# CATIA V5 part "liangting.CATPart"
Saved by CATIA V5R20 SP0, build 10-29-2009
Part number: liangting
Bounding box of the stored display mesh (mm): x -264.541 to 80, y -195 to 195, z -25 to 287.893
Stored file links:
  C:\Users\此生不败\Desktop\180211216李云飞\liangting.CATPart
  C:\Program Files\Dassault Systemes\B20\win_b64\startup\materials\Catalog.CATMaterial
  C:\Program Files\Dassault Systemes\B20\win_b64\startup\materials\bright_oak.jpg
  C:\Program Files\Dassault Systemes\B20\win_b64\startup\materials\alabaster.jpg
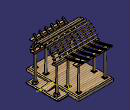
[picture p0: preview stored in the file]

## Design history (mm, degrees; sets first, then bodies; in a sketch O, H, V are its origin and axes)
Body1 (main body), material "Fence 3"
  Sketch1 on yz-plane, origin (0, 0, 0), H (0, 1, 0), V (0, 0, 1)
    line L1 (-120, -15) -> (120, -15)
    line L2 (120, -15) -> (120, -25)
    line L3 (120, -25) -> (-120, -25)
    line L4 (-120, -25) -> (-120, -15)
    distance O L1 = 15
    distance O L2 = 120
    distance O L4 = 120
    horizontal: L1 H, L3 H
    vertical: L2 V, L4 V
  Pad1: profile Sketch1, direction (1, 0, 0), length 80
  Sketch2 on xy-plane, origin (0, 0, 0), H (1, 0, 0), V (0, 1, 0)
    line L1 (-260, 195) -> (0, 195)
    line L2 (0, 195) -> (0, -195)
    line L3 (0, -195) -> (-260, -195)
    line L4 (-260, -195) -> (-260, 195)
    point P3 (0, -195)
    length L1 = 260
    distance O L1 = 195
    distance O L3 = 195
    horizontal: L1 H, L3 H
    vertical: L2 V, L4 V
    coincidence: P3 V
  Pad2: profile Sketch2, direction (0, 0, -1), length 25
  Chamfer1: length 6, angle 45, on edge [face of Pad2 from Sketch2.L1 | start face of Pad2]; edge [face of Pad2 from Sketch2.L4 | start face of Pad2]; edge [face of Pad2 from Sketch2.L3 | start face of Pad2]; edge [face of Pad2 from Sketch2.L2 | start face of Pad2]; edge [face of Pad1 from Sketch1.L1 | face of Pad1 from Sketch1.L2]; edge [face of Pad1 from Sketch1.L1 | end face of Pad1]; edge [face of Pad1 from Sketch1.L4 | face of Pad1 from Sketch1.L1]
  Sketch3 on xy-plane, origin (0, 0, 0), H (1, 0, 0), V (0, 1, 0)
    line L1 (-240, 175) -> (-215, 175)
    line L2 (-215, 175) -> (-215, 150)
    line L3 (-215, 150) -> (-240, 150)
    line L4 (-240, 150) -> (-240, 175)
    point P5 (-240, 95)
    line L5 (-240, 95) -> (-215, 95)
    line L6 (-215, 95) -> (-215, 70)
    line L7 (-215, 70) -> (-240, 70)
    line L8 (-240, 70) -> (-240, 95)
    point P7 (-215, 70)
    point P9 (-45, 175)
    line L9 (-45, 175) -> (-20, 175)
    line L10 (-20, 175) -> (-20, 150)
    line L11 (-20, 150) -> (-45, 150)
    line L12 (-45, 150) -> (-45, 175)
    point P13 (-45, 95)
    line L13 (-45, 95) -> (-20, 95)
    line L14 (-20, 95) -> (-20, 70)
    line L15 (-20, 70) -> (-45, 70)
    line L16 (-45, 70) -> (-45, 95)
    point P15 (-20, 70)
    line L17 (-240, -70) -> (-215, -70)
    line L18 (-215, -70) -> (-215, -95)
    line L19 (-215, -95) -> (-240, -95)
    line L20 (-240, -95) -> (-240, -70)
    point P19 (-215, -95)
    point P21 (-240, -149.7252)
    line L21 (-240, -149.7252) -> (-215, -149.7252)
    line L22 (-215, -149.7252) -> (-215, -174.7252)
    line L23 (-215, -174.7252) -> (-240, -174.7252)
    line L24 (-240, -174.7252) -> (-240, -149.7252)
    point P23 (-215, -174.7252)
    point P24 (-240, -174.7252)
    point P25 (-45.1012, -70)
    line L25 (-45.1012, -70) -> (-20.1012, -70)
    line L26 (-20.1012, -70) -> (-20.1012, -95)
    line L27 (-20.1012, -95) -> (-45.1012, -95)
    line L28 (-45.1012, -95) -> (-45.1012, -70)
    point P27 (-20.1012, -95)
    point P29 (-45, -150)
    line L29 (-45, -150) -> (-20, -150)
    line L30 (-20, -150) -> (-20, -175)
    line L31 (-20, -175) -> (-45, -175)
    line L32 (-45, -175) -> (-45, -150)
    point P31 (-20, -175)
    distance O L15 = 70
    distance O L25 = 70
    distance O L11 = 150
    distance O L29 = 150
    distance P24 P31 = 220.0002
    horizontal: L1 H, L3 H, L5 H, L7 H, L9 H, L11 H, L13 H, L15 H, L17 H, L19 H, L21 H, L23 H, L25 H, L27 H, L29 H, L31 H
    vertical: L2 V, L4 V, L6 V, L8 V, L10 V, L12 V, L14 V, L16 V, L18 V, L20 V, L22 V, L24 V, L26 V, L28 V, L30 V, L32 V
    coincidence: P5 L4, P7 L2, P9 L1, P13 L12, P13 L5, P15 L10, P15 L7, P19 L2, P21 L4, P23 L2, P25 L17, P27 L19, P29 L12, P31 L10
  Sketch4 on xy-plane, origin (0, 0, 0), H (1, 0, 0), V (0, 1, 0)
  Sketch5 on xy-plane, origin (0, 0, 0), H (1, 0, 0), V (0, 1, 0)
  Pad3: profile Sketch3, direction (0, 0, 1), length 6
  Chamfer2: length 3, angle 45, on end face of Pad3 (x8); edge [face of Pad3 from Sketch3.L30 | end face of Pad3]; edge [face of Pad3 from Sketch3.L29 | end face of Pad3]; edge [face of Pad3 from Sketch3.L32 | end face of Pad3]; edge [face of Pad3 from Sketch3.L31 | end face of Pad3]
  Sketch6 on xy-plane, origin (0, 0, 0), H (1, 0, 0), V (0, 1, 0)
    point P1 (50, 80.7583)
    point P2 (56.5, 92.0167)
    point P3 (43.5, 92.0167)
    point P4 (37, 80.7583)
    point P5 (43.5, 69.5)
    point P6 (56.5, 69.5)
    point P7 (63, 80.7583)
    point P8 (50, 92.0167)
    line L1 (56.5, 92.0167) -> (43.5, 92.0167)
    line L2 (43.5, 92.0167) -> (37, 80.7583)
    line L3 (37, 80.7583) -> (43.5, 69.5)
    line L4 (43.5, 69.5) -> (56.5, 69.5)
    line L5 (56.5, 69.5) -> (63, 80.7583)
    line L6 (63, 80.7583) -> (56.5, 92.0167)
    construction line L7 (50, 80.7583) -> (50, 92.0167)
    construction circle A1 centre (50, 80.7583) radius 13
    construction arc A2 centre (56.5, 69.5) radius 13 from (43.5, 69.5) to (63, 80.7583) cw
    construction arc A3 centre (43.5, 92.0167) radius 13 from (37, 80.7583) to (56.5, 92.0167) ccw
    reference projected line E1 (0, -195) -> (0, 195) from edge [face of Pad2 from Sketch2.L2 | face of Chamfer1]
    axis line L8 (-50, 0) -> (130, 0)
    point P9 (-50, 0)
    point P11 (43.5, -92.0167)
    point P12 (56.5, -92.0167)
    line L9 (56.5, -92.0167) -> (43.5, -92.0167)
    point P13 (56.5, -92.0167)
    point P14 (63, -80.7583)
    line L10 (63, -80.7583) -> (56.5, -92.0167)
    point P15 (37, -80.7583)
    point P16 (43.5, -92.0167)
    line L11 (43.5, -92.0167) -> (37, -80.7583)
    point P17 (43.5, -69.5)
    point P18 (37, -80.7583)
    line L12 (37, -80.7583) -> (43.5, -69.5)
    point P19 (63, -80.7583)
    point P20 (56.5, -69.5)
    line L13 (56.5, -69.5) -> (63, -80.7583)
    point P21 (56.5, -69.5)
    point P22 (43.5, -69.5)
    line L14 (43.5, -69.5) -> (56.5, -69.5)
    distance P4 E1 = 37
    distance H L4 = 69.5
    vertical: L7 V
    coincidence: A1 P2, A1 P3, A1 P4, A1 P5, A1 P6, A1 P7, A2 P1, A3 P1, P9 H, P11 P16, P12 P13, P14 P19, P15 P18, P17 P22, P20 P21
    midpoint: P8 L1
    parallelism: L1 L4
    horizontal: L8 H
    symmetry: P3 P11 L8, P2 P12 L8, L1 L9 L8, P2 P13 L8, P7 P14 L8, L6 L10 L8, P4 P15 L8, P3 P16 L8, L2 L11 L8, P5 P17 L8, P4 P18 L8, L3 L12 L8, P7 P19 L8, P6 P20 L8, L5 L13 L8, P6 P21 L8, P5 P22 L8, L4 L14 L8
  Pad4: profile Sketch6, direction (0, 0, -1), length 15
  Draft1: PullDir start face of Pad4, Angle 20, SupportToDraft (face of Pad4 from Sketch6.L4; face of Pad4 from Sketch6.L9; face of Pad4 from Sketch6.L10; face of Pad4 from Sketch6.L5; face of Pad4 from Sketch6.L13; face of Pad4 from Sketch6.L14; face of Pad4 from Sketch6.L6; face of Pad4 from Sketch6.L1; face of Pad4 from Sketch6.L11; face of Pad4 from Sketch6.L12; face of Pad4 from Sketch6.L2; face of Pad4 from Sketch6.L3), Neutral (start face of Pad4; start face of Pad4)
  Chamfer3: length 3, angle 45, on start face of Pad4 (x2)
  Sketch7 on xy-plane, origin (0, 0, 0), H (1, 0, 0), V (0, 1, 0)
    circle A1 centre (50, -80) radius 6
    circle A2 centre (50, 80) radius 6
    circle A3 centre (-31.597, 82.2668) radius 5.8004
    axis line L1 (-321.9031, 0) -> (215.1091, 0)
    point P4 (-321.9031, 0)
    circle A4 centre (-31.597, -82.2668) radius 5.8004
    circle A5 centre (-31.597, 163.3167) radius 6
    circle A6 centre (-31.597, -164.5217) radius 6
    circle A7 centre (-228.6837, -164.5217) radius 6
    circle A8 centre (-225.2523, -82.2668) radius 6
    circle A9 centre (-228.6837, 82.2668) radius 6
    circle A10 centre (-228.6837, 163.3167) radius 6
    coincidence: P4 H
    horizontal: L1 H
    symmetry: A3 A4 L1
  Pad5: profile Sketch7, direction (0, 0, 1), length 180
  Draft2: PullDir start face of Pad4, Angle 1, SupportToDraft (face of Pad5 from Sketch7.A9; face of Pad5 from Sketch7.A10; face of Pad5 from Sketch7.A8; face of Pad5 from Sketch7.A7; face of Pad5 from Sketch7.A6; face of Pad5 from Sketch7.A4; face of Pad5 from Sketch7.A3; face of Pad5 from Sketch7.A5; face of Pad5 from Sketch7.A2; face of Pad5 from Sketch7.A1), Neutral (end face of Pad5; end face of Pad5; end face of Pad5; end face of Pad5; end face of Pad5; end face of Pad5; end face of Pad5; end face of Pad5; end face of Pad5; end face of Pad5)
  Plane1: type Offset, RefPlane xy-plane, Offset 195
  Sketch8 on Plane1, origin (0, 0, 195), H (1, 0, 0), V (0, 1, 0)
    line L1 (-258.4621, 173.5465) -> (1.5379, 173.5465)
    line L2 (1.5379, 173.5465) -> (1.5379, 153.6415)
    line L3 (1.5379, 153.6415) -> (-258.4621, 153.6415)
    line L4 (-258.4621, 153.6415) -> (-258.4621, 173.5465)
    point P5 (-258.4621, 89.5724)
    line L5 (-258.4621, 89.5724) -> (77.2142, 89.5724)
    line L6 (77.2142, 89.5724) -> (77.2142, 71.5335)
    line L7 (77.2142, 71.5335) -> (-258.4621, 71.5335)
    line L8 (-258.4621, 71.5335) -> (-258.4621, 89.5724)
    point P9 (-258.4621, -70.2894)
    line L9 (-258.4621, -70.2894) -> (77.2142, -70.2894)
    line L10 (77.2142, -70.2894) -> (77.2142, -91.4385)
    line L11 (77.2142, -91.4385) -> (-258.4621, -91.4385)
    line L12 (-258.4621, -91.4385) -> (-258.4621, -70.2894)
    point P11 (77.2142, -91.4385)
    point P13 (-258.4621, -154.2636)
    line L13 (-258.4621, -154.2636) -> (1.5379, -154.2636)
    line L14 (1.5379, -154.2636) -> (1.5379, -172.9245)
    line L15 (1.5379, -172.9245) -> (-258.4621, -172.9245)
    line L16 (-258.4621, -172.9245) -> (-258.4621, -154.2636)
    point P15 (1.5379, -172.9245)
    length L1 = 260
    horizontal: L1 H, L3 H, L5 H, L7 H, L9 H, L11 H, L13 H, L15 H
    vertical: L2 V, L4 V, L6 V, L8 V, L10 V, L12 V, L14 V, L16 V
    coincidence: P5 L4, P9 L4, P11 L6, P13 L4, P15 L2
  Pad6: profile Sketch8, direction (0, 0, -1), length 15
  Chamfer4: length 10, angle 45, on edge [end face of Pad6 | face of Pad6 from Sketch8.L4]; edge [end face of Pad6 | face of Pad6 from Sketch8.L8]; edge [end face of Pad6 | face of Pad6 from Sketch8.L12]; edge [end face of Pad6 | face of Pad6 from Sketch8.L16]; edge [end face of Pad6 | face of Pad6 from Sketch8.L2]; edge [end face of Pad6 | face of Pad6 from Sketch8.L6]; edge [end face of Pad6 | face of Pad6 from Sketch8.L10]; edge [end face of Pad6 | face of Pad6 from Sketch8.L14]
  Sketch9 on Plane1, origin (0, 0, 195), H (1, 0, 0), V (0, 1, 0)
    construction arc A1 centre (-195.6927, 84.3318) radius 180.5052 from (-15.7984, 69.4938) to (-43.3023, 181.0753) ccw
    point P1 (-195.6927, 84.3318)
    arc A2 centre (-15.7984, 69.4938) radius 6.2816 from (-9.538, 68.9775) to (-22.0588, 70.0102) cw
    arc A3 centre (-43.3023, 181.0753) radius 6.2816 from (-48.6056, 177.7086) to (-37.9991, 184.442) cw
    arc A4 centre (-195.6927, 84.3318) radius 174.2236 from (-22.0588, 70.0102) to (-48.6056, 177.7086) ccw
    arc A5 centre (-195.6927, 84.3318) radius 186.7868 from (-37.9991, 184.442) to (-9.538, 68.9775) cw
    point P4 (-22.0588, 70.0102)
    point P5 (-48.6056, 177.7086)
    point P6 (-37.9991, 184.442)
    point P7 (-9.538, 68.9775)
    axis line L1 (-277.8354, 0) -> (225.1602, 0)
    point P8 (-277.8354, 0)
    point P10 (-9.538, -68.9775)
    point P11 (-37.9991, -184.442)
    point P12 (-195.6927, -84.3318)
    arc A6 centre (-195.6927, -84.3318) radius 186.7868 from (-37.9991, -184.442) to (-9.538, -68.9775) ccw
    point P13 (-48.6056, -177.7086)
    point P14 (-22.0588, -70.0102)
    point P15 (-195.6927, -84.3318)
    arc A7 centre (-195.6927, -84.3318) radius 174.2236 from (-22.0588, -70.0102) to (-48.6056, -177.7086) cw
    point P16 (-22.0588, -70.0102)
    point P17 (-9.538, -68.9775)
    arc A8 centre (-15.7984, -69.4938) radius 6.2816 from (-9.538, -68.9775) to (-22.0588, -70.0102) ccw
    point P19 (-37.9991, -184.442)
    point P20 (-48.6056, -177.7086)
    arc A9 centre (-43.3023, -181.0753) radius 6.2816 from (-48.6056, -177.7086) to (-37.9991, -184.442) ccw
    radius A3 = 6.2816
    tangency: A4 A3, A3 A5, A5 A2, A2 A4
    concentricity: A4 P1, A5 P1
    coincidence: P8 H, P10 P17, P11 P19, P13 P20, P14 P16
    horizontal: L1 H
    symmetry: P7 P10 L1, P6 P11 L1, P1 P12 L1, A5 A6 L1, P5 P13 L1, P4 P14 L1, P1 P15 L1, A4 A7 L1, P4 P16 L1, P7 P17 L1, A2 A8 L1, P6 P19 L1, P5 P20 L1, A3 A9 L1
  Pad7: profile Sketch9, direction (0, 0, 1), length 8
  RectPattern1: of Pad7, direction 1 instances 6, spacing 43, along end face of Pad7 reversed
  Chamfer5: length 3, angle 45, on face of RectPattern1 (x6); edge [face of RectPattern1 | face of RectPattern1] (x4); edge [face of Pad7 from Sketch9.A7 | end face of Pad7]; edge [face of Pad7 from Sketch9.A4 | end face of Pad7]
  Plane2: type Offset, RefPlane yz-plane, Offset 58
  Sketch10 on Plane2, origin (58, 0, 0), H (0, 1, 0), V (0, 0, 1)
    arc A1 centre (0, 194.4169) radius 72.9336 from (72.9307, 195.0707) to (-72.9307, 195.0707) ccw
    point P1 (0, 194.4169)
    arc A2 centre (0, 194.4169) radius 82.9416 from (82.9391, 195.0707) to (-82.9391, 195.0707) ccw
    line L1 (-82.9391, 195.0707) -> (-72.9307, 195.0707)
    line L2 (72.9307, 195.0707) -> (82.9391, 195.0707)
    coincidence: P1 V, L1 L2
    horizontal: L1 H, L2 H
  Pad8: profile Sketch10, direction (1, 0, 0), length 5
  RectPattern2: of Pad8, direction 1 instances 8, spacing 41, along axis of face of Pad8 from Sketch10.A2 reversed
  Chamfer6: length 2, angle 45, on face of Pad8 from Sketch10.A2
  Chamfer7: length 2, angle 45, on face of RectPattern2
  Chamfer8: length 2, angle 45, on edge [face of RectPattern2 | face of RectPattern2]
  Chamfer9: length 2, angle 45, on edge [face of RectPattern2 | face of RectPattern2]
  Chamfer10: length 2, angle 45, on edge [face of RectPattern2 | face of RectPattern2]
  Chamfer11: length 2, angle 45, on face of RectPattern2
  Chamfer12: length 2, angle 45, on edge [face of RectPattern2 | face of RectPattern2]
  Chamfer13: length 2, angle 45, on edge [face of RectPattern2 | face of RectPattern2]
  Sketch11 on zx-plane, origin (0, 0, 0), H (-1, 0, 0), V (0, 0, 1)
    line L1 (-70, -16) -> (0, -3)
    point P1 (0, -3)
    point P2 (-70, -16)
    distance P2 V = 70
    distance P2 H = 16
    distance P1 H = 3
    coincidence: P1 V
  Stiffener1: ThicknessValue 50, ExtendedProfile Sketch11, ThicknessTop 0
  Chamfer14: length 2, angle 45, on edge [face of Stiffener1 | face of Stiffener1] (x2)
  Sketch12 on yz-plane, origin (0, 0, 0), H (0, 1, 0), V (0, 0, 1)
    circle A1 centre (-87.3446, 208.2213) radius 5
  Pad9: profile Sketch12, direction (-1, 0, 0), length 250, opposite side length 80
  Sketch13 on zx-plane, origin (0, 0, 0), H (-1, 0, 0), V (0, 0, 1)
    line L1 (-93.1278, 194.5458) -> (271.9449, 194.5458)
    horizontal: L1 H
  CircPattern1: of Pad9, instances 13, angular step 13.5, axis from Sketch13.L1
  Fillet1: radius 2.5, on start face of Pad9; face of CircPattern1 (x9); edge [face of CircPattern1 | face of CircPattern1] (x3)
  Fillet2: radius 2.5, on face of CircPattern1 (x8); edge [face of CircPattern1 | face of CircPattern1] (x5); edge [end face of Pad9 | face of Pad9 from Sketch12.A1]
  Fillet3: radius 2.5, on edge [face of Pad9 from Sketch12.A1 | start face of Pad9]; face of CircPattern1 (x4); edge [face of CircPattern1 | face of CircPattern1] (x20); edge [end face of Pad9 | face of Pad9 from Sketch12.A1]
Current feature: Fillet2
